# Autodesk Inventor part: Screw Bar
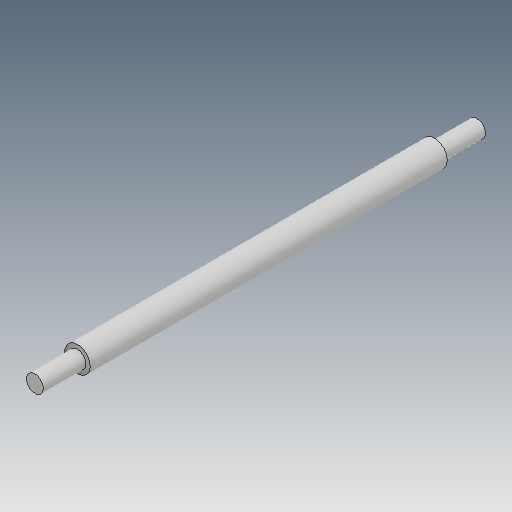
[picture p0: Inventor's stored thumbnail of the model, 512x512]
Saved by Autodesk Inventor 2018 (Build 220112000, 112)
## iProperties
Created: 2016-03
Part Number: Screw Bar
Material: Generic
Document SubType Name: Modeling
Designer: Sandeep
Density: 1 g/cm^3
Appearance: Default
Author: Sandeep
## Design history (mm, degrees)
sketch "Sketch1"
  geometry: L1 (-104, 2)-(-94, 2); L2 (-94, 2)-(-94, 3); L3 (-94, 3)-(-10, 3); L4 (-10, 3)-(-10, 2); L5 (-10, 2)-(0, 2); L6 (0, 2)-(0, 0); L7 (-104, 2)-(-104, 0); L8 (-104, 0)-(0, 0); L9 (0, 0)-(21.698, 0)
  constraints: 18 end point, 4 perpendicular, 3 horizontal, 2 point on line, 1 vertical
  dimensions: "d0" = 4 diameter of L5 L9; "d1" = 6 diameter of L3 L9; "d2" = 10 distance of L4.end L5.end; "d3" = 10 distance of L1.start L1.end; "d4" = 104 distance between parallel lines of L7 L6
revolve "Revolution1" sketch "Sketch1" stored, may be unused: angle "d5" = 90 deg
body "Solid1"
